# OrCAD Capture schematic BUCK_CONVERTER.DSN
size A; title: GhostScript Configuration Demo; rev: A; company: EMA Design Automation; note: EMA-12345678; note: 225 Tech park Dr; note: Rochester, NY
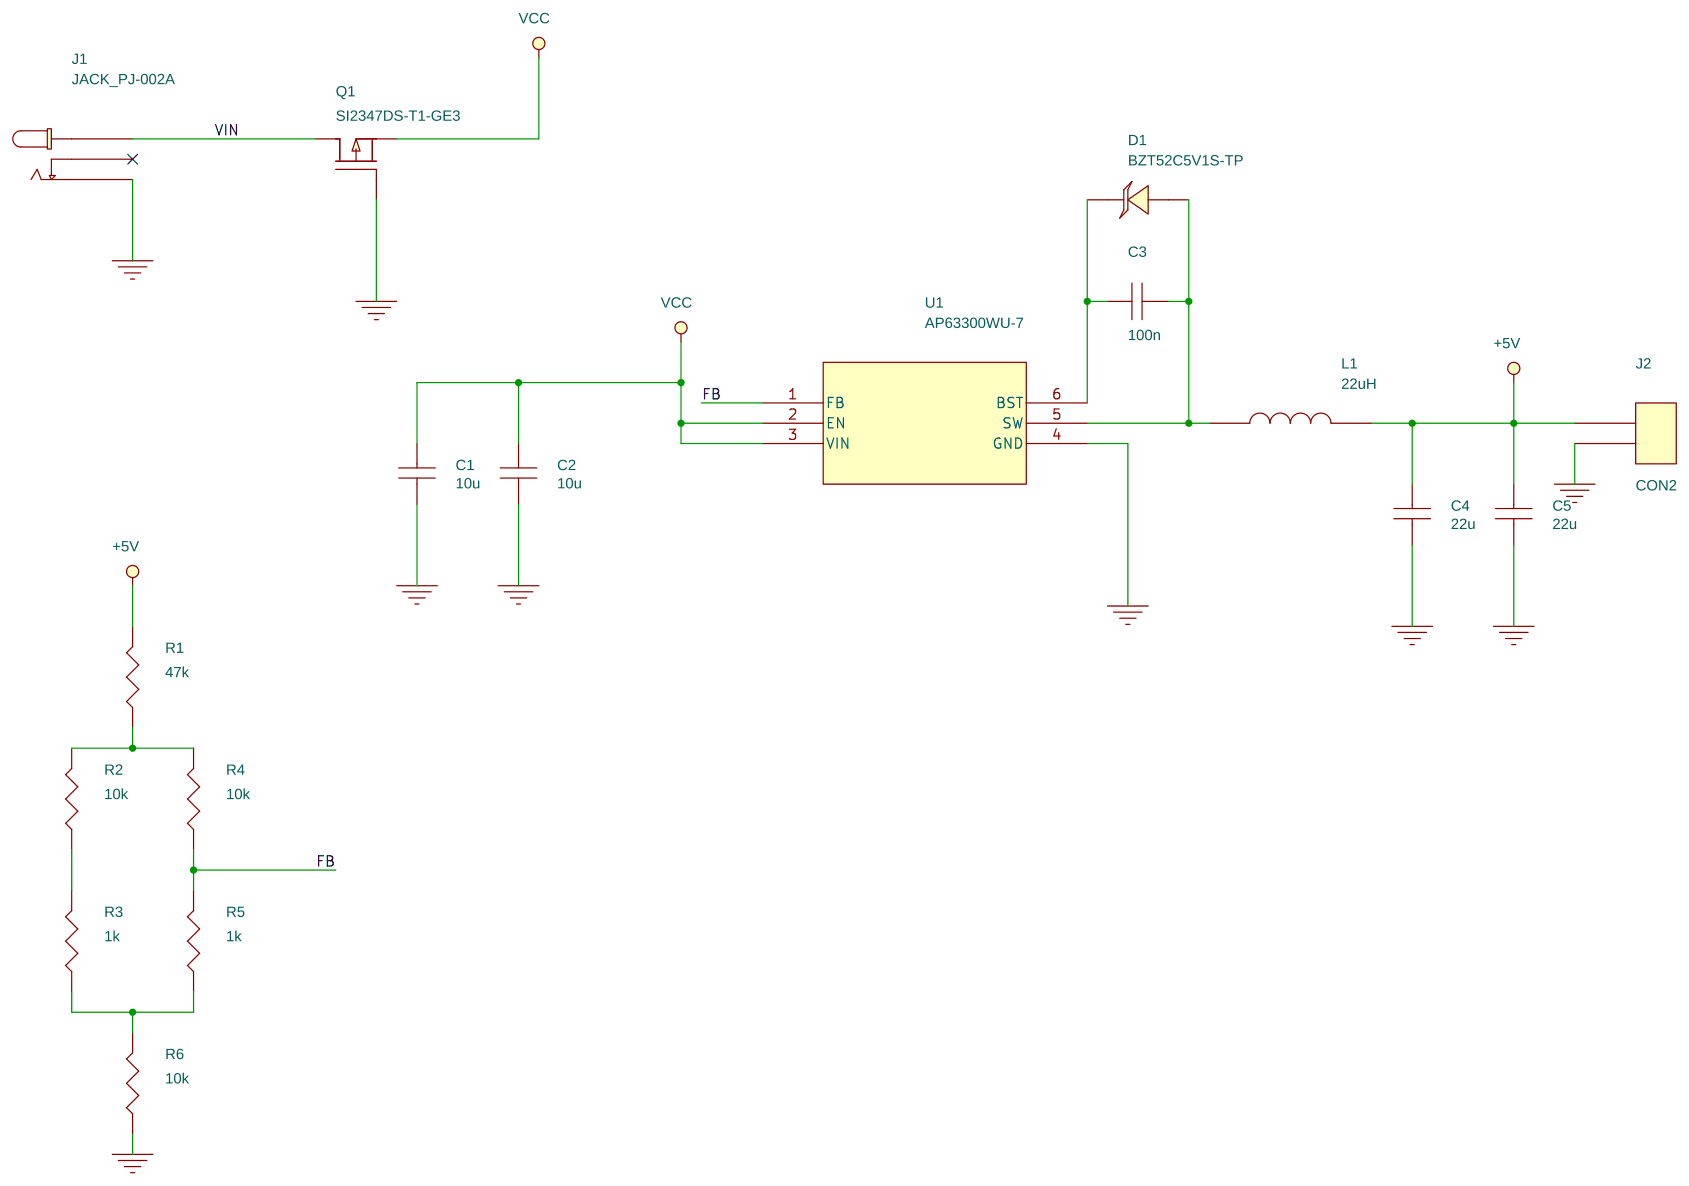
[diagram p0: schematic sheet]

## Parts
C1  10u  [SMC0805]
C2  10u  [SMC0805]
C3  100n  [SMC0603]
C4  22u  [1210]
C5  22u  [1210]
D1  BZT52C5V1S-TP  [SOD87]
J1  JACK_PJ-002A  [PJ-002A_CUD]
J2  CON2  [JUMPER2]
L1  22uH  [WE-PD_1260_1245_1280_121054]
Q1  SI2347DS-T1-GE3  [SOT_7DS-T1-GE3_VIS]
R1  47k  [SMR0603]
R2  10k  [SMR0603]
R3  1k  [SMR0603]
R4  10k  [SMR0603]
R5  1k  [SMR0603]
R6  10k  [SMR0603]
U1  AP63300WU-7  [TSOT6_AP63300WU-7_DIO]

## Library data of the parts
C1 C2 = CAP_NP: Manufacturer Name: Samsung Electro-Mechanics; Manufacturer Part Number: CL21A106KAYNNNG; Manufacturer_Part_Number: CL21A106KAYNNNG; Mfr_Name: Samsung Electro-Mechanics
C3 = CAP_NP: Manufacturer Name: KYOCERA AVX; Manufacturer Part Number: 06035C104JAT2A; Manufacturer_Part_Number: 06035C104JAT2A; Mfr_Name: KYOCERA AVX
C4 C5 = CAP_NP: Manufacturer Name: Samsung Electro-Mechanics; Manufacturer Part Number: CL32B226KAJNFNE; Manufacturer_Part_Number: CL32B226KAJNFNE; Mfr_Name: Samsung Electro-Mechanics
D1 = DIODE_TVS: Manufacturer Name: Micro Commercial Co; Mfr_Name: Micro Commercial Co
J1 = PJ-002A: Distributor Id: Digi-Key; Distributor Part Number: CP-002A-ND; Manufacturer Name: CUI Devices; Source Id: UL
J2 = CON2: Manufacturer Name: Sullins Connector Solutions; Manufacturer Part Number: S7000-ND; Manufacturer_Part_Number: S7000-ND; Mfr_Name: Sullins Connector Solutions
L1 = 7447709220_0: Manufacturer Name: W眉rth Elektronik; Manufacturer Part Number: 7447709220; Part Number: 7447709220; Source Id: SamacSys
Q1 = MOSFET_P_0: Distributor Part Number: SI2347DS-T1-GE3TR-ND; Manufacturer Name: Vishay Siliconix; Mfr_Name: Vishay Siliconix
R1 = RESISTOR: Manufacturer Name: Susumu; Manufacturer Part Number: RG16P47.0KBCT-ND; Manufacturer_Part_Number: RG16P47.0KBCT-ND; Mfr_Name: Susumu
R2 R4 R6 = RESISTOR: Manufacturer Name: Susumu; Manufacturer Part Number: RR08P10.0KDCT-ND; Manufacturer_Part_Number: RR08P10.0KDCT-ND; Mfr_Name: Susumu
R3 R5 = RESISTOR: Manufacturer Name: Susumu; Manufacturer Part Number: RR08P1.0KDCT-ND; Manufacturer_Part_Number: RR08P1.0KDCT-ND; Mfr_Name: Susumu
U1 = AP63300WU-7

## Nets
+5V: C4.1 C5.1 J2.1 L1.2 R1.2
GND: C1.2 C2.2 C4.2 C5.2 J1.2 J2.2 Q1.1(GATE) R6.1 U1.4(GND)
VCC: C1.1 C2.1 Q1.2(SOURCE) U1.2(EN) U1.3(VIN)
VIN: J1.1 Q1.3(DRAIN)
FB: R4.1 R5.2 U1.1(FB)
N00909: C3.2 D1.2(ANODE) L1.1 U1.5(SW)
N01043: C3.1 D1.1(CATHODE) U1.6(BST)
N03479: R3.1 R5.1 R6.2
N03507: R2.1 R3.2
N03511: R1.1 R2.2 R4.2

Not connected (* = marked no-connect by the designer): J1 3*
